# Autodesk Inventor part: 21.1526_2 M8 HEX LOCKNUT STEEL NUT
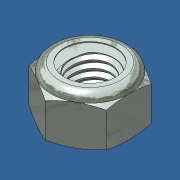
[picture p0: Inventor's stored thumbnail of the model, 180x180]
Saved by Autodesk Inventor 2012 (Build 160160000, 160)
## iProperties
Created: 2014-10
Part Number: 21.1526_2 M8 HEX LOCKNUT STEEL NUT
Material: Steel
Document SubType Name: Modeling
Designer: Admin
Density: 7.85 g/cm^3
Mass: 5.44973 g
Surface Area: 9.19726 cm^2
Volume: 0.694233 cm^3
Author: Admin
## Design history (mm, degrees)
feature "Base1"
body "Solid1"
